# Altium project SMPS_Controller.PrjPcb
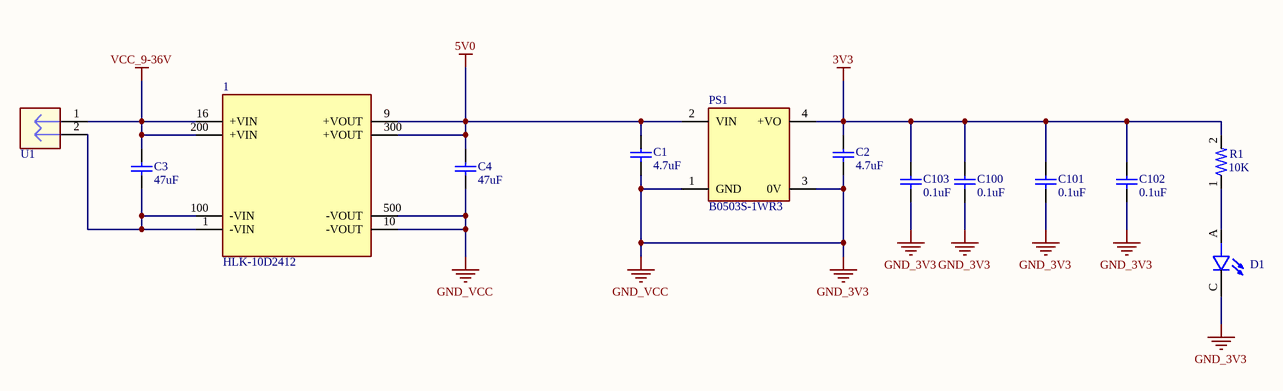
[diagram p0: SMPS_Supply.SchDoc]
11 sheets, 245 parts. Net scope: flat (ports and power ports of the same name join across sheets).
Board file: SMPS_Controller.PcbDoc
Sheets:
  SMPS_Supply.SchDoc
  SMPS_Connector.SchDoc
  SMPS_Voltage_1.SchDoc
  SMPS_Voltage_2.SchDoc
  SMPS_Voltage_3.SchDoc
  SMPS_Voltage_4.SchDoc
  SMPS_ADC_1.SchDoc
  SMPS_ADC_2.SchDoc
  SMPS_ADC_3.SchDoc
  SMPS_ADC_4.SchDoc
  SMPS_Signal.SchDoc

## Sheet SMPS_Supply.SchDoc
size A4; SheetNumber: 1; SheetTotal: 11

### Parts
1  HLK-10D2412  [HLK-10D2412]
C1  4.7uF  [CAP_0603]
C2  4.7uF  [CAP_0603]
C3  47uF  [CAP_1210]
C4  47uF  [CAP_1210]
C100  0.1uF  [CAP_0603]
C101  0.1uF  [CAP_0603]
C102  0.1uF  [CAP_0603]
C103  0.1uF  [CAP_0603]
D1  led_0603  [led_0603]  (value not drawn)
PS1  B0503S-1WR3  [B0503S-1W]
R1  10K  [RESC1608X50N]
U1  DG142R-5.08-02P  [DG142R-5.08-02P]  (value not drawn)

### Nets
3V3: C2.1 C100.1 C101.1 C102.1 C103.1 PS1.4(+VO) R1.2
5V0: 1.9(+VOUT) 1.300(+VOUT) C1.1 C4.2 PS1.2(VIN)
GND_3V3: 1.10(-VOUT) 1.500(-VOUT) C1.2 C2.2 C4.1 C100.2 C101.2 C102.2 C103.2 D1.C PS1.1(GND) PS1.3(0V)  [also labelled GND_VCC]
VCC_9-36V: 1.16(+VIN) 1.200(+VIN) C3.2 U1.1
Net1_1: 1.1(-VIN) 1.100(-VIN) C3.1 U1.2
NetD1_A: D1.A R1.1

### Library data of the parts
1 = HLK-10D2412: Isolated Module DC DC Converter Input: 9-24V   output: +12; MP: A1205S-2W; MF: Traco Power
C1 C2 C100-C103 = CAP_0603
C3 C4 = CAP_1210
D1 = led_0603: LED Indication - Discrete 3.1V 0603 _1608 Metric_; MP: LTW-C191TLA; MF: Lite-On
PS1 = B0505S-1WR3: Isolated Module DC DC Converter 1 Output 5V 200mA 4.5V - 5.5V Input; MF: Mornsun America, LLC
R1 = RES_0603: 1% 0.1W; MP: 1-2176071-4
U1 = DG142R-5.08-02P: DG129-5.0-03P-14-00AH

## Sheet SMPS_Connector.SchDoc
size A4; SheetNumber: 2; SheetTotal: 11
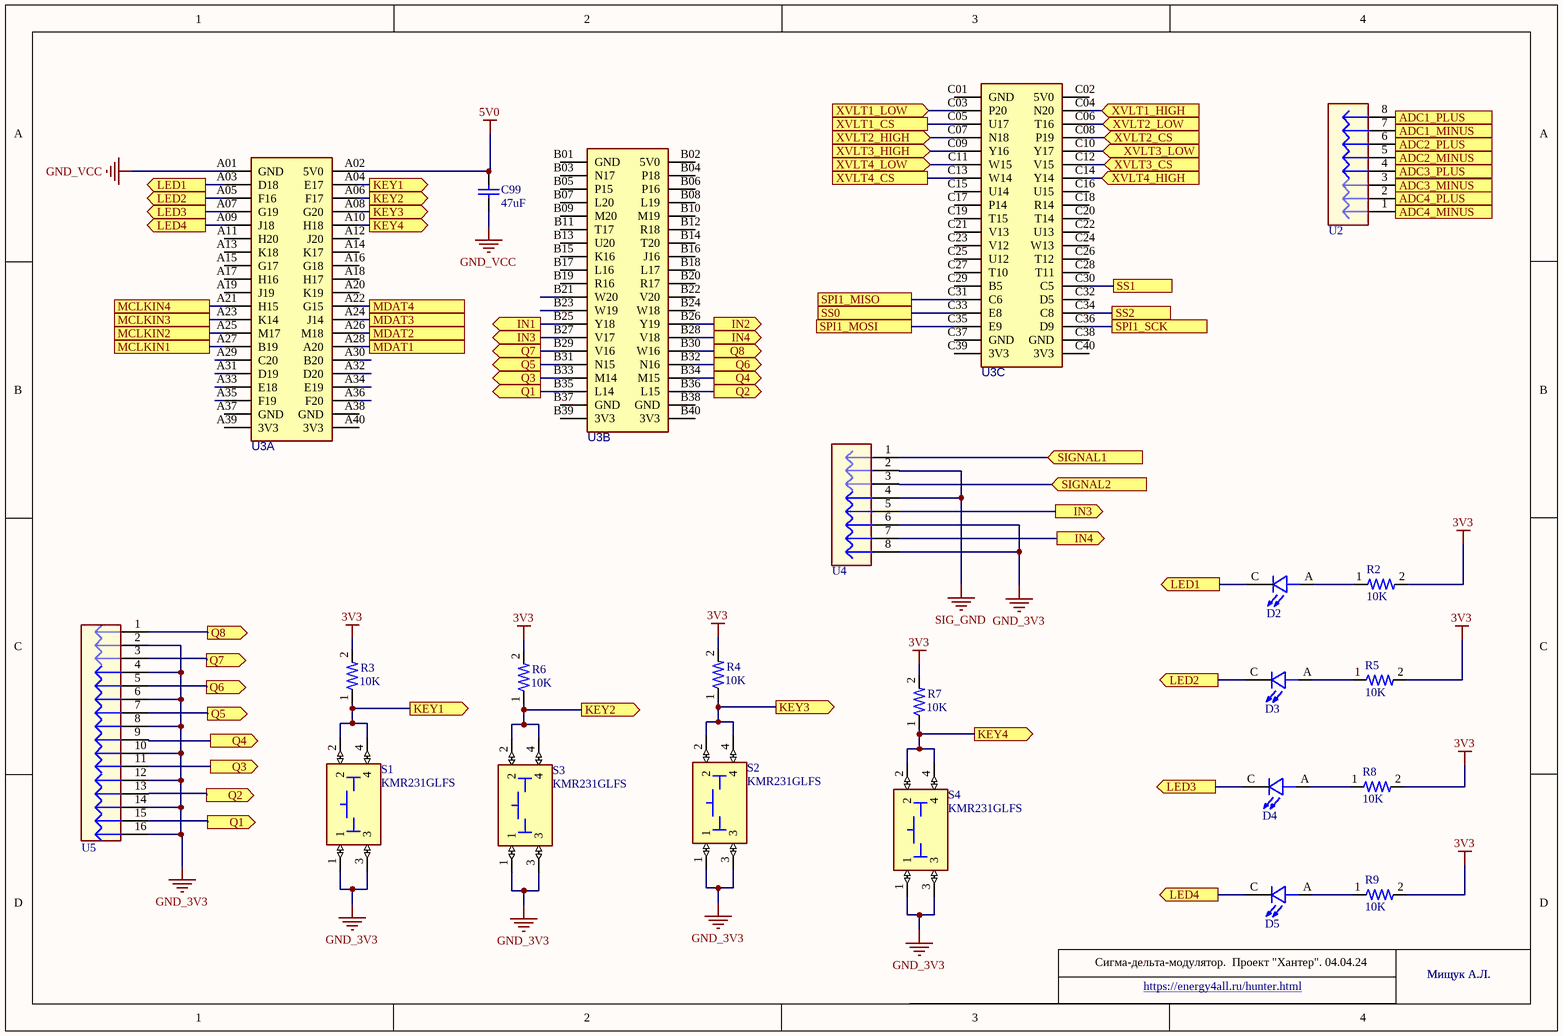
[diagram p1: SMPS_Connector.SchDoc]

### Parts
C99  47uF  [CAP_1210]
D2  led_0603  [led_0603]  (value not drawn)
D3  led_0603  [led_0603]  (value not drawn)
D4  led_0603  [led_0603]  (value not drawn)
D5  led_0603  [led_0603]  (value not drawn)
R2  10K  [RESC1608X50N]
R3  10K  [RESC1608X50N]
R4  10K  [RESC1608X50N]
R5  10K  [RESC1608X50N]
R6  10K  [RESC1608X50N]
R7  10K  [RESC1608X50N]
R8  10K  [RESC1608X50N]
R9  10K  [RESC1608X50N]
S1  KMR231GLFS  [KMR231GLFS]
S2  KMR231GLFS  [KMR231GLFS]
S3  KMR231GLFS  [KMR231GLFS]
S4  KMR231GLFS  [KMR231GLFS]
U2  DG142R-5.08-10P  [DG142R-5.08-10P]  (value not drawn)
U3  LGA506  [AC7020C]  (value not drawn)  (parts A,B,C of 3)
U4  DG141R-2.54-08P  [DG141R-2.54-08P]  (value not drawn)
U5  DG141R-2.54-16P  [DG141R-2.54-16P]  (value not drawn)

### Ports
ADC1_MINUS (out), ADC1_PLUS (out), ADC2_MINUS (out), ADC2_PLUS (out), ADC3_MINUS (out), ADC3_PLUS (out), ADC4_MINUS (out), ADC4_PLUS (out), IN1 (out), IN2 (out), IN3 (out), IN4 (out), KEY1 (out), KEY2 (out), KEY3 (out), KEY4 (out), LED1 (out), LED2 (out), LED3 (out), LED4 (out), MCLKIN1, MCLKIN2, MCLKIN3, MCLKIN4, MDAT1, MDAT2, MDAT3, MDAT4, Q1 (out), Q2 (out), Q3 (out), Q4 (out), Q5 (out), Q6 (out), Q7 (out), Q8 (out), SIGNAL1 (in), SIGNAL2 (in), SPI1_MISO, SPI1_MOSI, SPI1_SCK, SS0, SS1, SS2, XVLT1_CS, XVLT1_HIGH (in), XVLT1_LOW (in), XVLT2_CS (in), XVLT2_HIGH (in), XVLT2_LOW (in), XVLT3_CS (in), XVLT3_HIGH (in), XVLT3_LOW (in), XVLT4_CS, XVLT4_HIGH (in), XVLT4_LOW (in)

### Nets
3V3: R2.2 R3.2 R4.2 R5.2 R6.2 R7.2 R8.2 R9.2
5V0: C99.2 U3.A02(5V0)
GND_3V3: C99.1 S1.1 S1.3 S2.1 S2.3 S3.1 S3.3 S4.1 S4.3 U3.A01(GND) U4.6 U4.8 U5.2 U5.4 U5.6 U5.8 U5.10 U5.12 U5.14 U5.16  [also labelled GND_VCC]
SIG_GND: U4.2 U4.4
NetD2_A: D2.A R2.1
NetD2_C: D2.C U3.A03(D18) ; port LED1
NetD3_A: D3.A R5.1
NetD3_C: D3.C U3.A05(F16) ; port LED2
NetD4_A: D4.A R8.1
NetD4_C: D4.C U3.A07(G19) ; port LED3
NetD5_A: D5.A R9.1
NetD5_C: D5.C U3.A09(J18) ; port LED4
NetR3_1: R3.1 S1.2 S1.4 U3.A04(E17) ; port KEY1
NetR4_1: R4.1 S2.2 S2.4 U3.A08(G20) ; port KEY3
NetR6_1: R6.1 S3.2 S3.4 U3.A06(F17) ; port KEY2
NetR7_1: R7.1 S4.2 S4.4 U3.A10(H18) ; port KEY4
NetR46_1: U2.2 ; port ADC4_PLUS
NetR47_1: U3.A22(G15) ; port MDAT4
NetR48_1: U3.A21(H15) ; port MCLKIN4
NetR49_1: U2.1 ; port ADC4_MINUS
NetR52_1: U2.8 ; port ADC1_PLUS
NetR53_1: U3.A28(A20) ; port MDAT1
NetR54_1: U3.A27(B19) ; port MCLKIN1
NetR55_1: U2.7 ; port ADC1_MINUS
NetR58_1: U2.6 ; port ADC2_PLUS
NetR59_1: U3.A26(M18) ; port MDAT2
NetR60_1: U3.A25(M17) ; port MCLKIN2
NetR61_1: U2.5 ; port ADC2_MINUS
NetR64_1: U2.4 ; port ADC3_PLUS
NetR65_1: U3.A24(J14) ; port MDAT3
NetR66_1: U3.A23(K14) ; port MCLKIN3
NetR67_1: U2.3 ; port ADC3_MINUS
NetR70_1: U4.1 ; port SIGNAL1
NetR71_1: U4.3 ; port SIGNAL2
NetU3_B25: U3.B25(Y18) ; port IN1
NetU3_B26: U3.B26(Y19) ; port IN2
NetU3_B27: U3.B27(V17) U4.5 ; port IN3
NetU3_B28: U3.B28(V18) U4.7 ; port IN4
NetU3_B29: U3.B29(V16) U5.3 ; port Q7
NetU3_B30: U3.B30(W16) U5.1 ; port Q8
NetU3_B31: U3.B31(N15) U5.7 ; port Q5
NetU3_B32: U3.B32(N16) U5.5 ; port Q6
NetU3_B33: U3.B33(M14) U5.11 ; port Q3
NetU3_B34: U3.B34(M15) U5.9 ; port Q4
NetU3_B35: U3.B35(L14) U5.15 ; port Q1
NetU3_B36: U3.B36(L15) U5.13 ; port Q2
NetU3_C03: U3.C03(P20) ; port XVLT1_LOW
NetU3_C04: U3.C04(N20) ; port XVLT1_HIGH
NetU3_C05: U3.C05(U17) ; port XVLT1_CS
NetU3_C06: U3.C06(T16) ; port XVLT2_LOW
NetU3_C07: U3.C07(N18) ; port XVLT2_HIGH
NetU3_C08: U3.C08(P19) ; port XVLT2_CS
NetU3_C09: U3.C09(Y16) ; port XVLT3_HIGH
NetU3_C10: U3.C10(Y17) ; port XVLT3_LOW
NetU3_C11: U3.C11(W15) ; port XVLT4_LOW
NetU3_C12: U3.C12(V15) ; port XVLT3_CS
NetU3_C13: U3.C13(W14) ; port XVLT4_CS
NetU3_C14: U3.C14(Y14) ; port XVLT4_HIGH
NetU3_C30: U3.C30(C5) ; port SS1
NetU3_C31: U3.C31(C6) ; port SPI1_MISO
NetU3_C33: U3.C33(E8) ; port SS0
NetU3_C34: U3.C34(C8) ; port SS2
NetU3_C35: U3.C35(E9) ; port SPI1_MOSI
NetU3_C36: U3.C36(D9) ; port SPI1_SCK

Not connected (* = marked no-connect by the designer): U3 A11(H20) A12(J20) A13(K18) A14(K17) A15(G17) A16(G18) A17(H16) A18(H17) A19(J19) A20(K19) A29(C20) A30(B20) A31(D19) A32(D20) A33(E18) A34(E19) A35(F19) A36(F20) A37(GND) A38(GND) A39(3V3) A40(3V3) B01(GND) B02(5V0) B03(N17) B04(P18) B05(P15) B06(P16) B07(L20) B08(L19) B09(M20) B10(M19) B11(T17) B12(R18) B13(U20) B14(T20) B15(K16) B16(J16) B17(L16) B18(L17) B19(R16) B20(R17) B21(W20) B22(V20) B23(W19) B24(W18) B37(GND) B38(GND) B39(3V3) B40(3V3) C01(GND) C02(5V0) C15(U14) C16(U15) C17(P14) C18(R14) C19(T15) C20(T14) C21(V13) C22(U13) C23(V12) C24(W13) C25(U12) C26(T12) C27(T10) C28(T11) C29(B5) C32(D5) C37(GND) C38(GND) C39(3V3) C40(3V3)

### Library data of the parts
C99 = CAP_1210
D2-D5 = led_0603: as D1 on sheet SMPS_Supply
R2-R9 = RES_0603: 1% 0.1W; MP: 1-2176071-4
S1-S4 = KMR231GLFS: Tactile Switch SPST-NO Top Actuated Surface Mount; MF: C&K
U2 = DG142R-5.08-10P: DG129-5.0-03P-14-00AH
U3 = AC7020C
U4 = DG141R-2.54-08P: DG129-5.0-03P-14-00AH
U5 = DG141R-2.54-16P: DG129-5.0-03P-14-00AH

## Sheet SMPS_Voltage_1.SchDoc
size A4; SheetNumber: 3; SheetTotal: 11
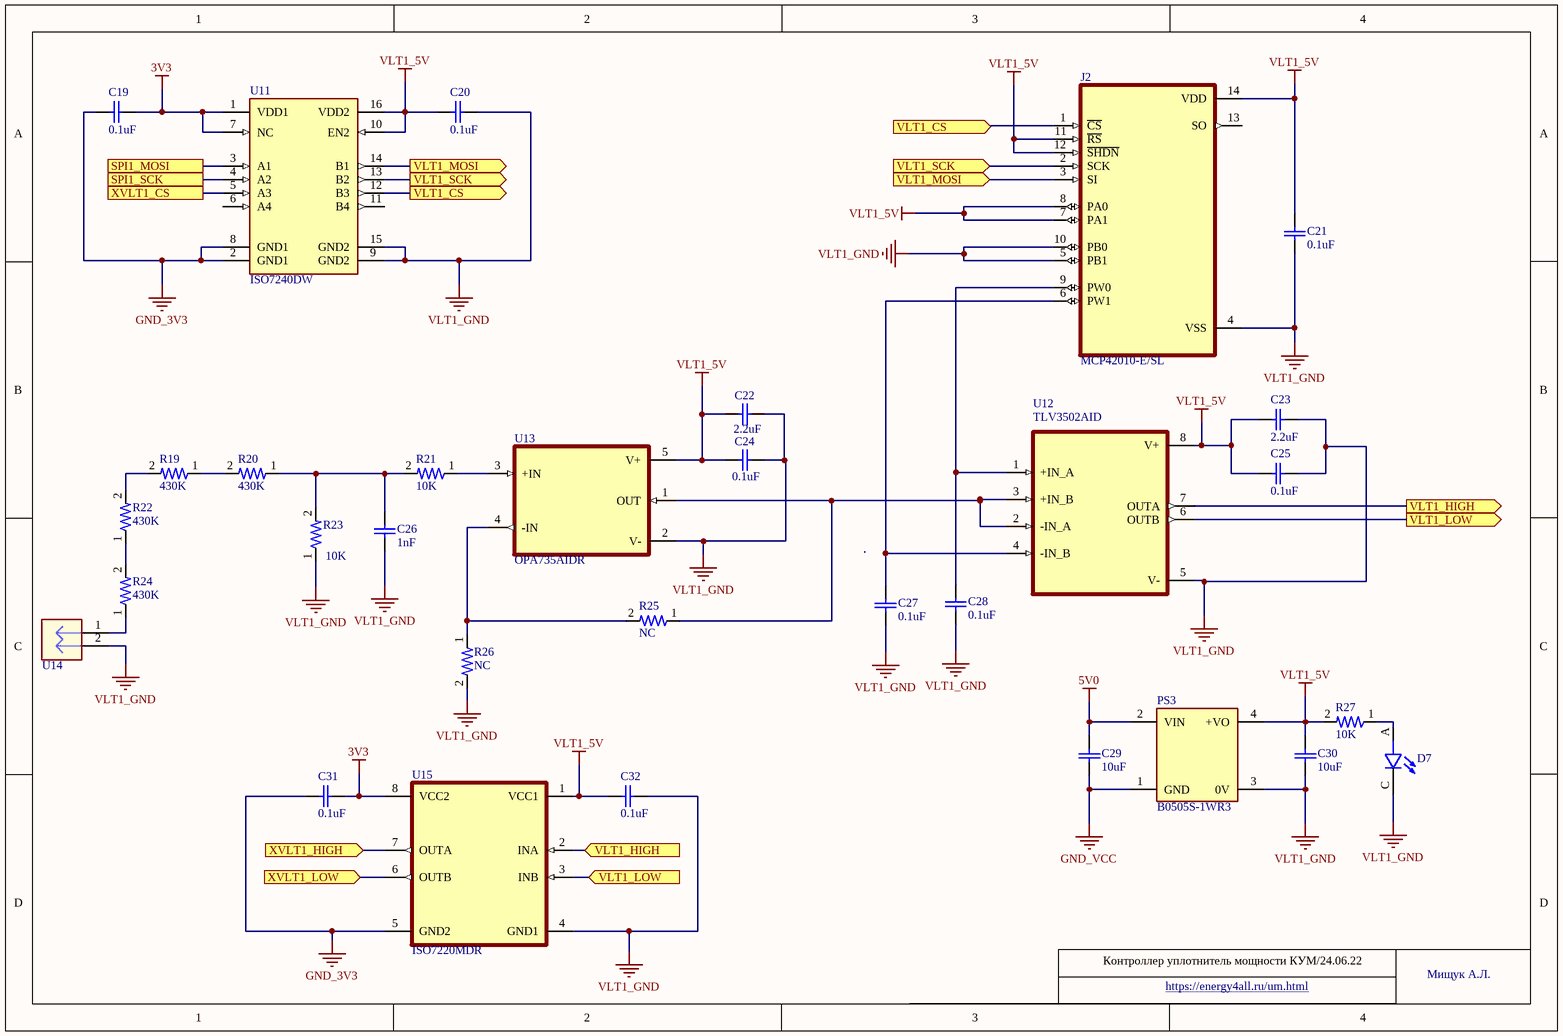
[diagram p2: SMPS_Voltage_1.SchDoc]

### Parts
C19  0.1uF  [CAP_0603]
C20  0.1uF  [CAP_0603]
C21  0.1uF  [CAP_0603]
C22  2.2uF  [CAP_0603]
C23  2.2uF  [CAP_0603]
C24  0.1uF  [CAP_0603]
C25  0.1uF  [CAP_0603]
C26  1nF  [CAP_0603]
C27  0.1uF  [CAP_0603]
C28  0.1uF  [CAP_0603]
C29  10uF  [CAP_0603]
C30  10uF  [CAP_0603]
C31  0.1uF  [CAP_0603]
C32  0.1uF  [CAP_0603]
D7  led_0603  [led_0603]  (value not drawn)
J2  MCP42010-E/SL  [SOP65P640X120-14N]
PS3  B0505S-1WR3  [B0503S-1W]
R19  430K  [RES_2512]
R20  430K  [RES_2512]
R21  10K  [RESC1608X50N]
R22  430K  [RES_2512]
R23  10K  [RES_1206]
R24  430K  [RES_2512]
R25  NC  [RESC1608X50N]
R26  NC  [RESC1608X50N]
R27  10K  [RESC1608X50N]
U11  ISO7240DW  [ISO7240DW]
U12  TLV3502AID  [TLV3502AID]
U13  OPA735AIDR  [OPA735AIDBVR]
U14  DG142R-5.08-02P  [DG142R-5.08-02P]  (value not drawn)
U15  ISO7220MDR  [ISO7220MDR]

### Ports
SPI1_MOSI, SPI1_SCK, VLT1_CS (in), VLT1_CS (out), VLT1_HIGH (in), VLT1_HIGH (out), VLT1_LOW (in), VLT1_LOW (out), VLT1_MOSI (in), VLT1_MOSI (out), VLT1_SCK (in), VLT1_SCK (out), XVLT1_CS, XVLT1_HIGH (in), XVLT1_LOW (in)

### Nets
3V3: C19.1 C31.1 U11.1(VDD1) U11.7(NC) U15.8(VCC2)
5V0: C29.2 PS3.2(VIN)
GND_3V3: C19.2 C29.1 C31.2 PS3.1(GND) U11.2(GND1) U11.8(GND1) U15.5(GND2)  [also labelled GND_VCC]
VLT1_5V: C20.2 C21.2 C22.1 C23.1 C24.1 C25.1 C30.2 C32.2 J2.7(PA1) J2.8(PA0) J2.11(~{RS}) J2.12(~{SHDN}) J2.14(VDD) PS3.4(+VO) R27.2 U11.10(EN2) U11.16(VDD2) U12.8(V+) U13.5(V+) U15.1(VCC1)
VLT1_GND: C20.1 C21.1 C22.2 C23.2 C24.2 C25.2 C26.2 C27.2 C28.2 C30.1 C32.1 D7.C J2.4(VSS) J2.5(PB1) J2.10(PB0) PS3.3(0V) R23.1 R26.2 U11.9(GND2) U11.15(GND2) U12.5(V-) U13.2(V-) U14.2 U15.4(GND1)
NetC26_1: C26.1 R20.1 R21.2 R23.2
NetC27_1: C27.1 J2.6(PW1) U12.4(-IN_B)
NetC28_1: C28.1 J2.9(PW0) U12.1(+IN_A)
NetD7_A: D7.A R27.1
NetJ2_1: J2.1(~{CS}) U11.12(B3) ; port VLT1_CS
NetJ2_2: J2.2(SCK) U11.13(B2) ; port VLT1_SCK
NetJ2_3: J2.3(SI) U11.14(B1) ; port VLT1_MOSI
NetR19_1: R19.1 R20.2
NetR19_2: R19.2 R22.2
NetR21_1: R21.1 U13.3(+IN)
NetR22_1: R22.1 R24.2
NetR24_1: R24.1 U14.1
NetR25_1: R25.1 U12.2(-IN_A) U12.3(+IN_B) U13.1(OUT)
NetR25_2: R25.2 R26.1 U13.4(-IN)
NetU3_C03: U15.6(OUTB) ; port XVLT1_LOW
NetU3_C04: U15.7(OUTA) ; port XVLT1_HIGH
NetU3_C05: U11.5(A3) ; port XVLT1_CS
NetU3_C35: U11.3(A1) ; port SPI1_MOSI
NetU3_C36: U11.4(A2) ; port SPI1_SCK
NetU12_6: U12.6(OUTB) U15.3(INB) ; port VLT1_LOW
NetU12_7: U12.7(OUTA) U15.2(INA) ; port VLT1_HIGH

Not connected (* = marked no-connect by the designer): J2 13(SO); U11 6(A4) 11(B4)

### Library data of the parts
C19-C32 = CAP_0603
D7 = led_0603: as D1 on sheet SMPS_Supply
J2 = MCP42010-E/SL: DIGITAL POT, 256 STEPS, SPI, 10KOHMS, DUAL CHANNEL ¦ Microchip Technology Inc. MCP42010-E/SL
PS3 = B0505S-1WR3: as PS1 on sheet SMPS_Supply
R19 R20 R22 R24 = RES_2512: 2512 1% 1W; MP: 1-2176071-4
R21 R25-R27 = RES_0603: 1% 0.1W; MP: 1-2176071-4
R23 = RES_1206: 1% 1/4W; MP: 1-2176071-4
U11 = ISO7240DW: MP: ISO7241CDWR
U12 = TLV3502AID: 4.5ns Rail-to-Rail Comparator; MF: Texas Instruments
U14 = DG142R-5.08-02P: DG129-5.0-03P-14-00AH
U15 = ISO7220MDR: Dual-channel, 2/0, 150-Mbps digital isolator 8-SOIC -40 to 125; MF: Texas Instruments

## Sheet SMPS_Voltage_2.SchDoc
size A4; SheetNumber: 4; SheetTotal: 11
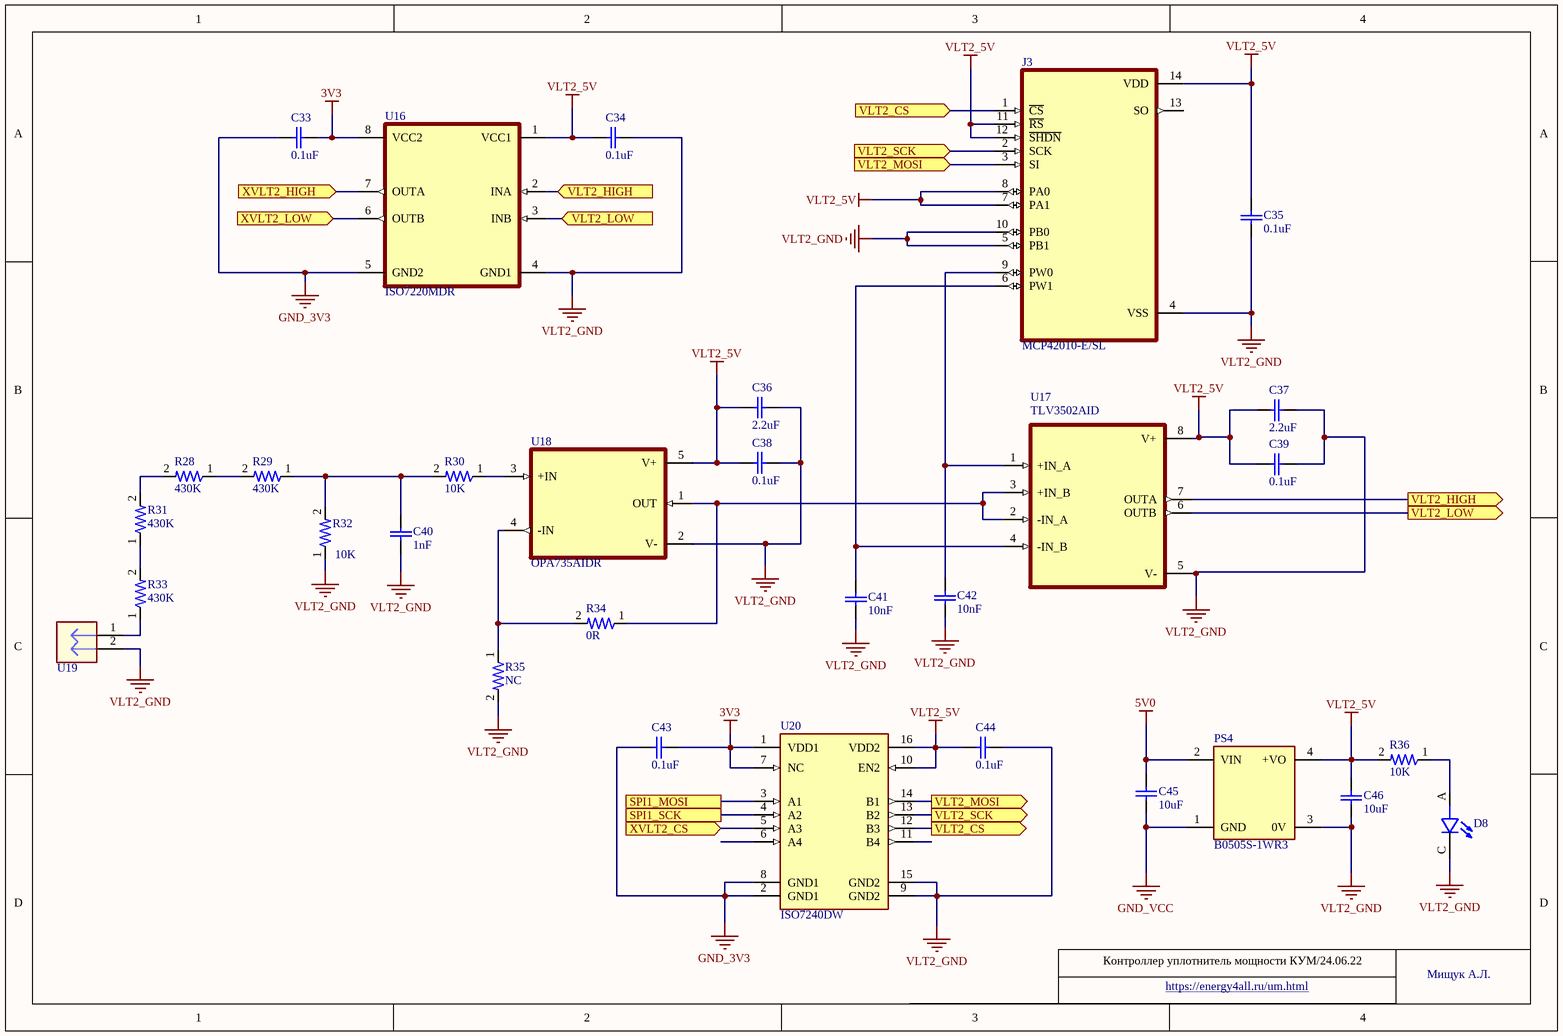
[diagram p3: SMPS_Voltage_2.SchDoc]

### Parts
C33  0.1uF  [CAP_0603]
C34  0.1uF  [CAP_0603]
C35  0.1uF  [CAP_0603]
C36  2.2uF  [CAP_0603]
C37  2.2uF  [CAP_0603]
C38  0.1uF  [CAP_0603]
C39  0.1uF  [CAP_0603]
C40  1nF  [CAP_0603]
C41  10nF  [CAP_0603]
C42  10nF  [CAP_0603]
C43  0.1uF  [CAP_0603]
C44  0.1uF  [CAP_0603]
C45  10uF  [CAP_0603]
C46  10uF  [CAP_0603]
D8  led_0603  [led_0603]  (value not drawn)
J3  MCP42010-E/SL  [SOP65P640X120-14N]
PS4  B0505S-1WR3  [B0503S-1W]
R28  430K  [RES_2512]
R29  430K  [RES_2512]
R30  10K  [RESC1608X50N]
R31  430K  [RES_2512]
R32  10K  [RES_1206]
R33  430K  [RES_2512]
R34  0R  [RESC1608X50N]
R35  NC  [RESC1608X50N]
R36  10K  [RESC1608X50N]
U16  ISO7220MDR  [ISO7220MDR]
U17  TLV3502AID  [TLV3502AID]
U18  OPA735AIDR  [OPA735AIDBVR]
U19  DG142R-5.08-02P  [DG142R-5.08-02P]  (value not drawn)
U20  ISO7240DW  [ISO7240DW]

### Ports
SPI1_MOSI, SPI1_SCK, VLT2_CS (in), VLT2_CS (out), VLT2_HIGH (in), VLT2_HIGH (out), VLT2_LOW (in), VLT2_LOW (out), VLT2_MOSI (in), VLT2_MOSI (out), VLT2_SCK (in), VLT2_SCK (out), XVLT2_CS (in), XVLT2_HIGH (in), XVLT2_LOW (in)

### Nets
3V3: C33.1 C43.1 U16.8(VCC2) U20.1(VDD1) U20.7(NC)
5V0: C45.2 PS4.2(VIN)
GND_3V3: C33.2 C43.2 C45.1 PS4.1(GND) U16.5(GND2) U20.2(GND1) U20.8(GND1)  [also labelled GND_VCC]
VLT2_5V: C34.2 C35.2 C36.1 C37.1 C38.1 C39.1 C44.2 C46.2 J3.7(PA1) J3.8(PA0) J3.11(~{RS}) J3.12(~{SHDN}) J3.14(VDD) PS4.4(+VO) R36.2 U16.1(VCC1) U17.8(V+) U18.5(V+) U20.10(EN2) U20.16(VDD2)
VLT2_GND: C34.1 C35.1 C36.2 C37.2 C38.2 C39.2 C40.2 C41.1 C42.1 C44.1 C46.1 D8.C J3.4(VSS) J3.5(PB1) J3.10(PB0) PS4.3(0V) R32.1 R35.2 U16.4(GND1) U17.5(V-) U18.2(V-) U19.2 U20.9(GND2) U20.15(GND2)
NetC40_1: C40.1 R29.1 R30.2 R32.2
NetC41_2: C41.2 J3.6(PW1) U17.4(-IN_B)
NetC42_2: C42.2 J3.9(PW0) U17.1(+IN_A)
NetD8_A: D8.A R36.1
NetJ3_1: J3.1(~{CS}) U20.12(B3) ; port VLT2_CS
NetJ3_2: J3.2(SCK) U20.13(B2) ; port VLT2_SCK
NetJ3_3: J3.3(SI) U20.14(B1) ; port VLT2_MOSI
NetR28_1: R28.1 R29.2
NetR28_2: R28.2 R31.2
NetR30_1: R30.1 U18.3(+IN)
NetR31_1: R31.1 R33.2
NetR33_1: R33.1 U19.1
NetR34_1: R34.1 U17.2(-IN_A) U17.3(+IN_B) U18.1(OUT)
NetR34_2: R34.2 R35.1 U18.4(-IN)
NetU3_C06: U16.6(OUTB) ; port XVLT2_LOW
NetU3_C07: U16.7(OUTA) ; port XVLT2_HIGH
NetU3_C08: U20.5(A3) ; port XVLT2_CS
NetU3_C35: U20.3(A1) ; port SPI1_MOSI
NetU3_C36: U20.4(A2) ; port SPI1_SCK
NetU16_2: U16.2(INA) U17.7(OUTA) ; port VLT2_HIGH
NetU16_3: U16.3(INB) U17.6(OUTB) ; port VLT2_LOW

Not connected (* = marked no-connect by the designer): J3 13(SO); U20 6(A4) 11(B4)

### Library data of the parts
C33-C46 = CAP_0603
D8 = led_0603: as D1 on sheet SMPS_Supply
J3 = MCP42010-E/SL: as J2 on sheet SMPS_Voltage_1
PS4 = B0505S-1WR3: as PS1 on sheet SMPS_Supply
R28 R29 R31 R33 = RES_2512: 2512 1% 1W; MP: 1-2176071-4
R30 R34-R36 = RES_0603: 1% 0.1W; MP: 1-2176071-4
R32 = RES_1206: 1% 1/4W; MP: 1-2176071-4
U16 = ISO7220MDR: as U15 on sheet SMPS_Voltage_1
U17 = TLV3502AID: as U12 on sheet SMPS_Voltage_1
U19 = DG142R-5.08-02P: DG129-5.0-03P-14-00AH
U20 = ISO7240DW: MP: ISO7241CDWR

## Sheet SMPS_Voltage_3.SchDoc
size A4; SheetNumber: 5; SheetTotal: 11
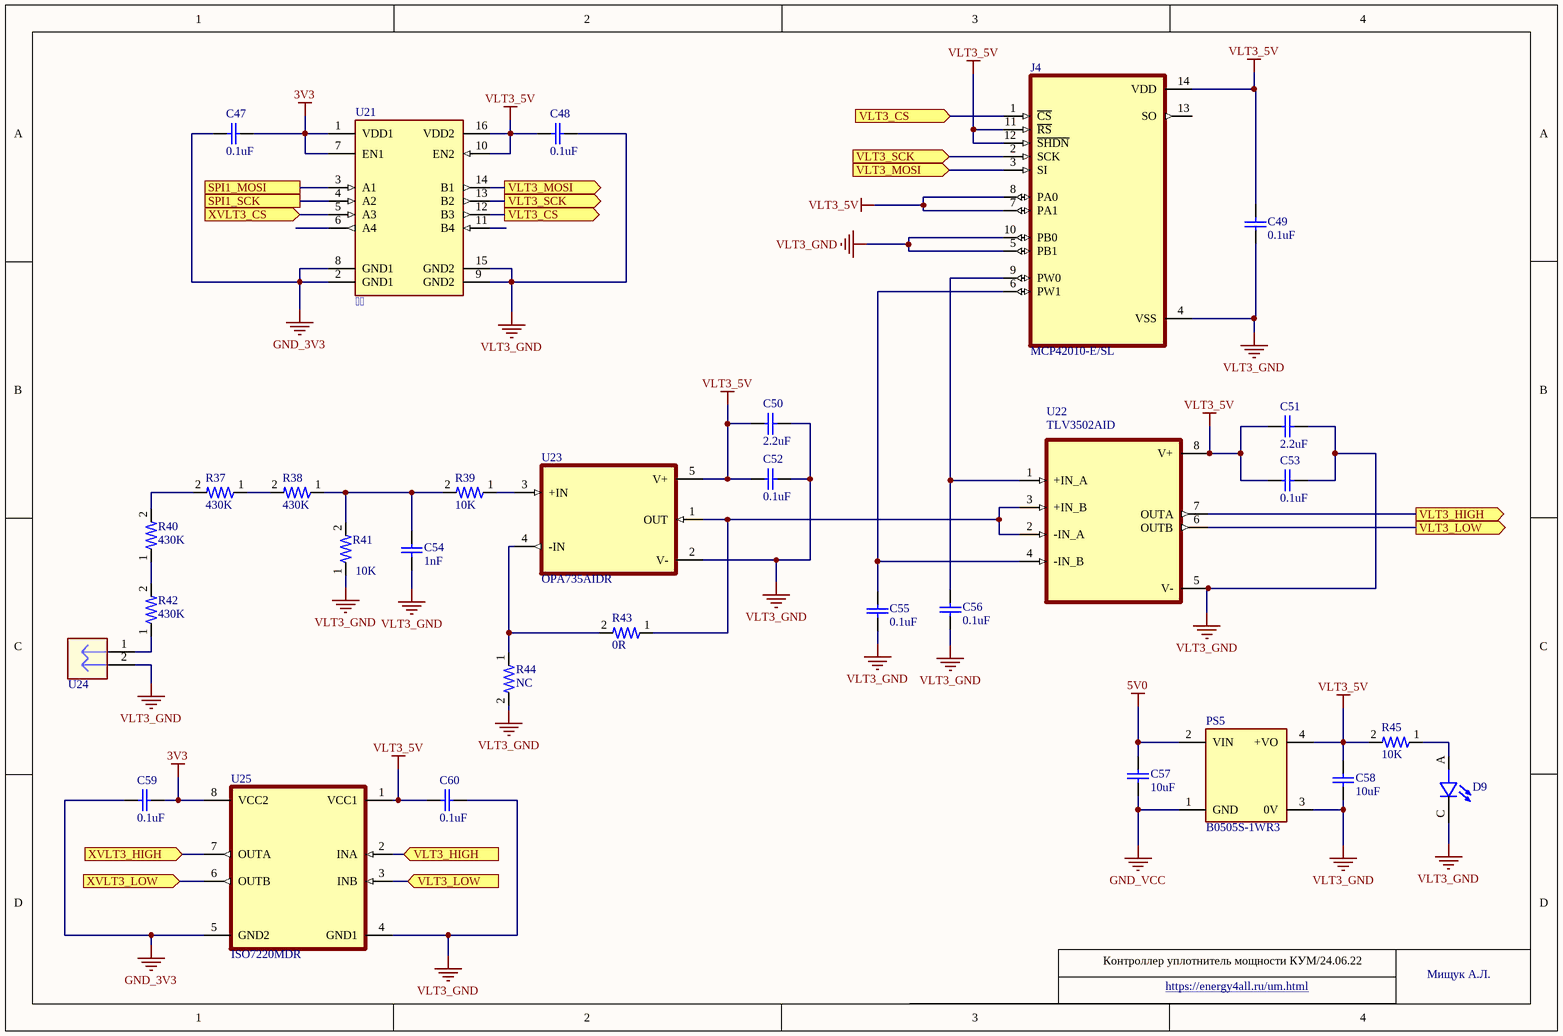
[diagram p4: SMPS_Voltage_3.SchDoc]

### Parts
C47  0.1uF  [CAP_0603]
C48  0.1uF  [CAP_0603]
C49  0.1uF  [CAP_0603]
C50  2.2uF  [CAP_0603]
C51  2.2uF  [CAP_0603]
C52  0.1uF  [CAP_0603]
C53  0.1uF  [CAP_0603]
C54  1nF  [CAP_0603]
C55  0.1uF  [CAP_0603]
C56  0.1uF  [CAP_0603]
C57  10uF  [CAP_0603]
C58  10uF  [CAP_0603]
C59  0.1uF  [CAP_0603]
C60  0.1uF  [CAP_0603]
D9  led_0603  [led_0603]  (value not drawn)
J4  MCP42010-E/SL  [SOP65P640X120-14N]
PS5  B0505S-1WR3  [B0503S-1W]
R37  430K  [RES_2512]
R38  430K  [RES_2512]
R39  10K  [RESC1608X50N]
R40  430K  [RES_2512]
R41  10K  [RES_1206]
R42  430K  [RES_2512]
R43  0R  [RESC1608X50N]
R44  NC  [RESC1608X50N]
R45  10K  [RESC1608X50N]
U21    [SI8641ED]
U22  TLV3502AID  [TLV3502AID]
U23  OPA735AIDR  [OPA735AIDBVR]
U24  DG142R-5.08-02P  [DG142R-5.08-02P]  (value not drawn)
U25  ISO7220MDR  [ISO7220MDR]

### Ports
SPI1_MOSI, SPI1_SCK, VLT3_CS (in), VLT3_CS (out), VLT3_HIGH (in), VLT3_HIGH (out), VLT3_LOW (in), VLT3_LOW (out), VLT3_MOSI (in), VLT3_MOSI (out), VLT3_SCK (in), VLT3_SCK (out), XVLT3_CS (in), XVLT3_HIGH (in), XVLT3_LOW (in)

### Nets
3V3: C47.1 C59.1 U21.1(VDD1) U21.7(EN1) U25.8(VCC2)
5V0: C57.2 PS5.2(VIN)
GND_3V3: C47.2 C57.1 C59.2 PS5.1(GND) U21.2(GND1) U21.8(GND1) U25.5(GND2)  [also labelled GND_VCC]
VLT3_5V: C48.2 C49.2 C50.1 C51.1 C52.1 C53.1 C58.2 C60.2 J4.7(PA1) J4.8(PA0) J4.11(~{RS}) J4.12(~{SHDN}) J4.14(VDD) PS5.4(+VO) R45.2 U21.10(EN2) U21.16(VDD2) U22.8(V+) U23.5(V+) U25.1(VCC1)
VLT3_GND: C48.1 C49.1 C50.2 C51.2 C52.2 C53.2 C54.2 C55.2 C56.2 C58.1 C60.1 D9.C J4.4(VSS) J4.5(PB1) J4.10(PB0) PS5.3(0V) R41.1 R44.2 U21.9(GND2) U21.15(GND2) U22.5(V-) U23.2(V-) U24.2 U25.4(GND1)
NetC54_1: C54.1 R38.1 R39.2 R41.2
NetC55_1: C55.1 J4.6(PW1) U22.4(-IN_B)
NetC56_1: C56.1 J4.9(PW0) U22.1(+IN_A)
NetD9_A: D9.A R45.1
NetJ4_1: J4.1(~{CS}) U21.12(B3) ; port VLT3_CS
NetJ4_2: J4.2(SCK) U21.13(B2) ; port VLT3_SCK
NetJ4_3: J4.3(SI) U21.14(B1) ; port VLT3_MOSI
NetR37_1: R37.1 R38.2
NetR37_2: R37.2 R40.2
NetR39_1: R39.1 U23.3(+IN)
NetR40_1: R40.1 R42.2
NetR42_1: R42.1 U24.1
NetR43_1: R43.1 U22.2(-IN_A) U22.3(+IN_B) U23.1(OUT)
NetR43_2: R43.2 R44.1 U23.4(-IN)
NetU3_C09: U25.7(OUTA) ; port XVLT3_HIGH
NetU3_C10: U25.6(OUTB) ; port XVLT3_LOW
NetU3_C12: U21.5(A3) ; port XVLT3_CS
NetU3_C35: U21.3(A1) ; port SPI1_MOSI
NetU3_C36: U21.4(A2) ; port SPI1_SCK
NetU22_6: U22.6(OUTB) U25.3(INB) ; port VLT3_LOW
NetU22_7: U22.7(OUTA) U25.2(INA) ; port VLT3_HIGH

Not connected (* = marked no-connect by the designer): J4 13(SO); U21 6(A4) 11(B4)

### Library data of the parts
C47-C60 = CAP_0603
D9 = led_0603: as D1 on sheet SMPS_Supply
J4 = MCP42010-E/SL: as J2 on sheet SMPS_Voltage_1
PS5 = B0505S-1WR3: as PS1 on sheet SMPS_Supply
R37 R38 R40 R42 = RES_2512: 2512 1% 1W; MP: 1-2176071-4
R39 R43-R45 = RES_0603: 1% 0.1W; MP: 1-2176071-4
R41 = RES_1206: 1% 1/4W; MP: 1-2176071-4
U21 = SI8641ED: General Purpose Digital Isolator 2500Vrms 4 Channel 150Mbps 35kV/Âµs CMTI 16-SOIC _0.154, 3.90mm Width_; MP: SI8641BB-B-IS1; MF: Silicon Labs
U22 = TLV3502AID: as U12 on sheet SMPS_Voltage_1
U24 = DG142R-5.08-02P: DG129-5.0-03P-14-00AH
U25 = ISO7220MDR: as U15 on sheet SMPS_Voltage_1

## Sheet SMPS_Voltage_4.SchDoc
size A4; SheetNumber: 6; SheetTotal: 11
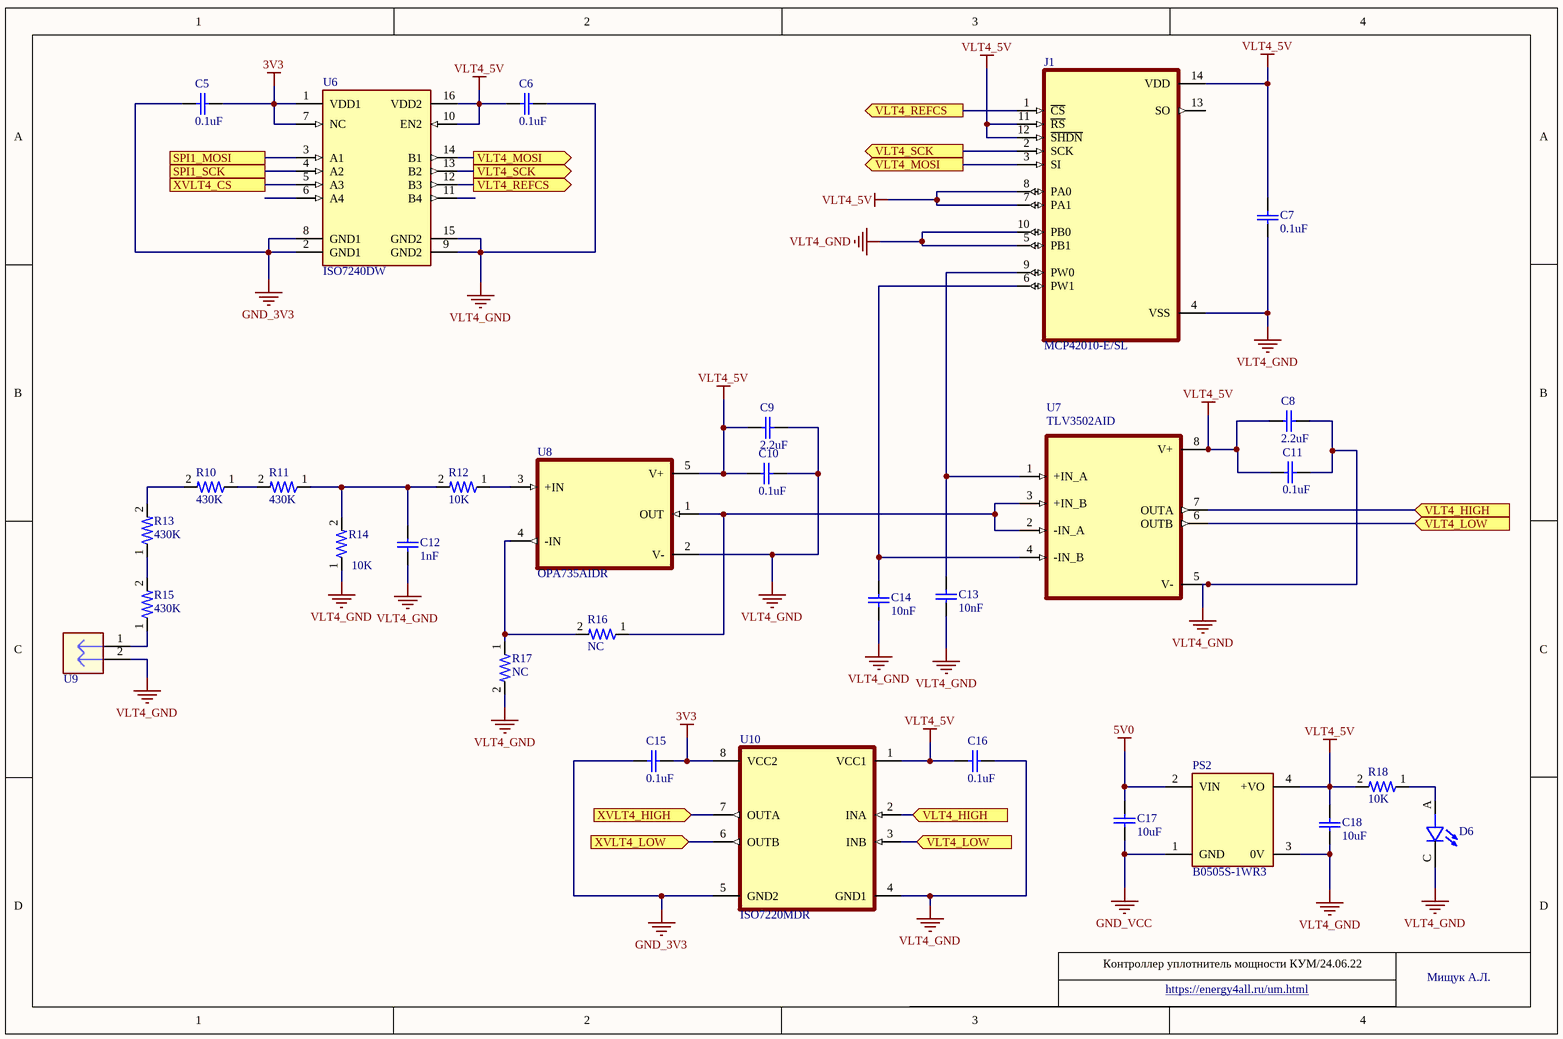
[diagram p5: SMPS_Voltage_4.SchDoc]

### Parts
C5  0.1uF  [CAP_0603]
C6  0.1uF  [CAP_0603]
C7  0.1uF  [CAP_0603]
C8  2.2uF  [CAP_0603]
C9  2.2uF  [CAP_0603]
C10  0.1uF  [CAP_0603]
C11  0.1uF  [CAP_0603]
C12  1nF  [CAP_0603]
C13  10nF  [CAP_0603]
C14  10nF  [CAP_0603]
C15  0.1uF  [CAP_0603]
C16  0.1uF  [CAP_0603]
C17  10uF  [CAP_0603]
C18  10uF  [CAP_0603]
D6  led_0603  [led_0603]  (value not drawn)
J1  MCP42010-E/SL  [SOP65P640X120-14N]
PS2  B0505S-1WR3  [B0503S-1W]
R10  430K  [RES_2512]
R11  430K  [RES_2512]
R12  10K  [RESC1608X50N]
R13  430K  [RES_2512]
R14  10K  [RES_1206]
R15  430K  [RES_2512]
R16  NC  [RESC1608X50N]
R17  NC  [RESC1608X50N]
R18  10K  [RESC1608X50N]
U6  ISO7240DW  [ISO7240DW]
U7  TLV3502AID  [TLV3502AID]
U8  OPA735AIDR  [OPA735AIDBVR]
U9  DG142R-5.08-02P  [DG142R-5.08-02P]  (value not drawn)
U10  ISO7220MDR  [ISO7220MDR]

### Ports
SPI1_MOSI, SPI1_SCK, VLT4_HIGH (in), VLT4_LOW (in), VLT4_MOSI (out), VLT4_REFCS (out), VLT4_SCK (out), XVLT4_CS, XVLT4_HIGH (in), XVLT4_LOW (in)

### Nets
3V3: C5.1 C15.1 U6.1(VDD1) U6.7(NC) U10.8(VCC2)
5V0: C17.2 PS2.2(VIN)
GND_3V3: C5.2 C15.2 C17.1 PS2.1(GND) U6.2(GND1) U6.8(GND1) U10.5(GND2)  [also labelled GND_VCC]
VLT4_5V: C6.2 C7.2 C8.1 C9.1 C10.1 C11.1 C16.2 C18.2 J1.7(PA1) J1.8(PA0) J1.11(~{RS}) J1.12(~{SHDN}) J1.14(VDD) PS2.4(+VO) R18.2 U6.10(EN2) U6.16(VDD2) U7.8(V+) U8.5(V+) U10.1(VCC1)
VLT4_GND: C6.1 C7.1 C8.2 C9.2 C10.2 C11.2 C12.2 C13.1 C14.2 C16.1 C18.1 D6.C J1.4(VSS) J1.5(PB1) J1.10(PB0) PS2.3(0V) R14.1 R17.2 U6.9(GND2) U6.15(GND2) U7.5(V-) U8.2(V-) U9.2 U10.4(GND1)
NetC12_1: C12.1 R11.1 R12.2 R14.2
NetC13_2: C13.2 J1.9(PW0) U7.1(+IN_A)
NetC14_1: C14.1 J1.6(PW1) U7.4(-IN_B)
NetD6_A: D6.A R18.1
NetJ1_1: J1.1(~{CS}) U6.12(B3) ; port VLT4_REFCS
NetJ1_2: J1.2(SCK) U6.13(B2) ; port VLT4_SCK
NetJ1_3: J1.3(SI) U6.14(B1) ; port VLT4_MOSI
NetR10_1: R10.1 R11.2
NetR10_2: R10.2 R13.2
NetR12_1: R12.1 U8.3(+IN)
NetR13_1: R13.1 R15.2
NetR15_1: R15.1 U9.1
NetR16_1: R16.1 U7.2(-IN_A) U7.3(+IN_B) U8.1(OUT)
NetR16_2: R16.2 R17.1 U8.4(-IN)
NetU3_C11: U10.6(OUTB) ; port XVLT4_LOW
NetU3_C13: U6.5(A3) ; port XVLT4_CS
NetU3_C14: U10.7(OUTA) ; port XVLT4_HIGH
NetU3_C35: U6.3(A1) ; port SPI1_MOSI
NetU3_C36: U6.4(A2) ; port SPI1_SCK
NetU7_6: U7.6(OUTB) U10.3(INB) ; port VLT4_LOW
NetU7_7: U7.7(OUTA) U10.2(INA) ; port VLT4_HIGH

Not connected (* = marked no-connect by the designer): J1 13(SO); U6 6(A4) 11(B4)

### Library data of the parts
C5-C18 = CAP_0603
D6 = led_0603: as D1 on sheet SMPS_Supply
J1 = MCP42010-E/SL: as J2 on sheet SMPS_Voltage_1
PS2 = B0505S-1WR3: as PS1 on sheet SMPS_Supply
R10 R11 R13 R15 = RES_2512: 2512 1% 1W; MP: 1-2176071-4
R12 R16-R18 = RES_0603: 1% 0.1W; MP: 1-2176071-4
R14 = RES_1206: 1% 1/4W; MP: 1-2176071-4
U6 = ISO7240DW: MP: ISO7241CDWR
U7 = TLV3502AID: as U12 on sheet SMPS_Voltage_1
U9 = DG142R-5.08-02P: DG129-5.0-03P-14-00AH
U10 = ISO7220MDR: as U15 on sheet SMPS_Voltage_1

## Sheet SMPS_ADC_1.SchDoc
size A4; SheetNumber: 7; SheetTotal: 11
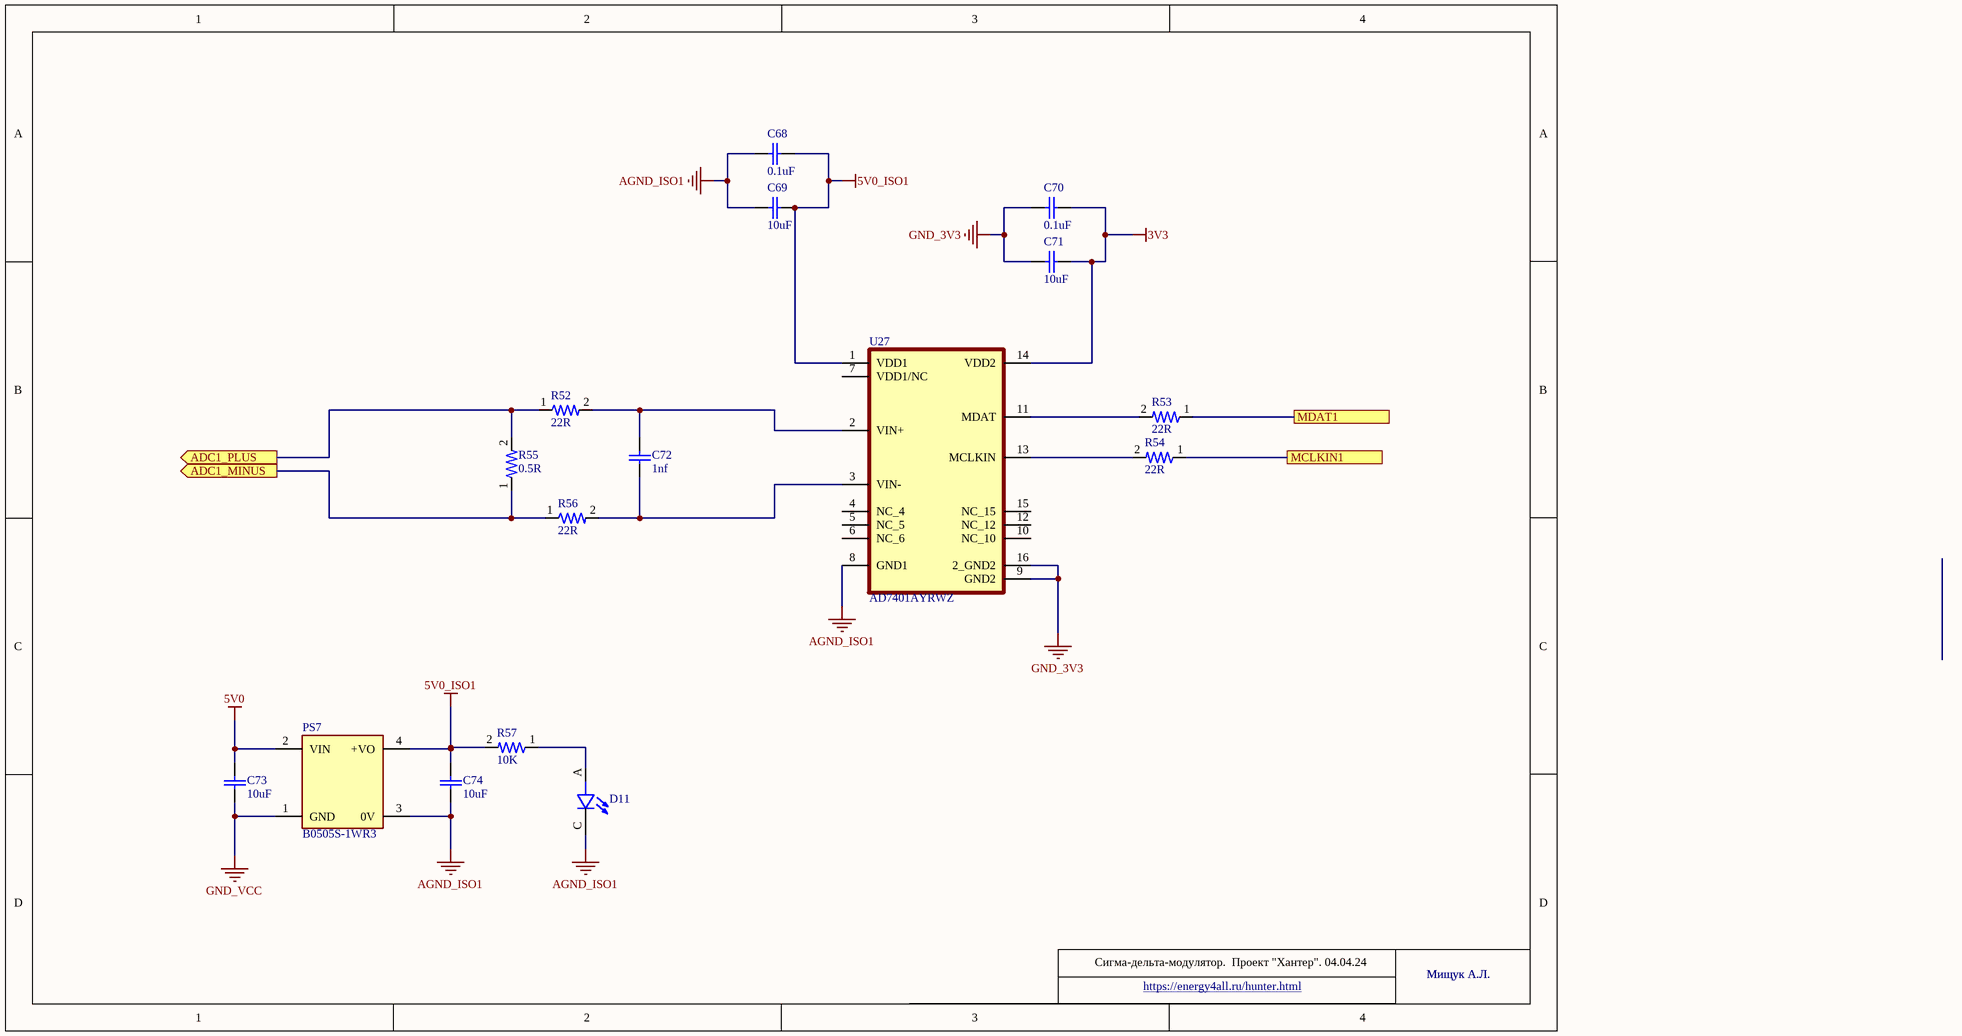
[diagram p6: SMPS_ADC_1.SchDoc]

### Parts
C68  0.1uF  [CAP_0603]
C69  10uF  [CAP_0603]
C70  0.1uF  [CAP_0603]
C71  10uF  [CAP_0603]
C72  1nf  [CAP_0603]
C73  10uF  [CAP_0603]
C74  10uF  [CAP_0603]
D11  led_0603  [led_0603]  (value not drawn)
PS7  B0505S-1WR3  [B0503S-1W]
R52  22R  [RESC1608X50N]
R53  22R  [RESC1608X50N]
R54  22R  [RESC1608X50N]
R55  0.5R  [RES_2512]
R56  22R  [RESC1608X50N]
R57  10K  [RESC1608X50N]
U27  AD7401AYRWZ  [AD7401AYRWZ]

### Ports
ADC1_MINUS (out), ADC1_PLUS (out), MCLKIN1, MDAT1

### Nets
3V3: C70.1 C71.1 U27.14(VDD2)
5V0: C73.2 PS7.2(VIN)
5V0_ISO1: C68.1 C69.1 C74.2 PS7.4(+VO) R57.2 U27.1(VDD1)
AGND_ISO1: C68.2 C69.2 C74.1 D11.C PS7.3(0V) U27.8(GND1)
GND_3V3: C70.2 C71.2 C73.1 PS7.1(GND) U27.9(GND2) U27.16(2_GND2)  [also labelled GND_VCC]
NetC72_1: C72.1 R56.2 U27.3(VIN-)
NetC72_2: C72.2 R52.2 U27.2(VIN+)
NetD11_A: D11.A R57.1
NetR52_1: R52.1 R55.2 ; port ADC1_PLUS
NetR53_1: R53.1 ; port MDAT1
NetR53_2: R53.2 U27.11(MDAT)
NetR54_1: R54.1 ; port MCLKIN1
NetR54_2: R54.2 U27.13(MCLKIN)
NetR55_1: R55.1 R56.1 ; port ADC1_MINUS

Not connected (* = marked no-connect by the designer): U27 4(NC_4) 5(NC_5) 6(NC_6) 7(VDD1/NC) 10(NC_10) 12(NC_12) 15(NC_15)

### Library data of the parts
C68-C74 = CAP_0603
D11 = led_0603: as D1 on sheet SMPS_Supply
PS7 = B0505S-1WR3: as PS1 on sheet SMPS_Supply
R52-R54 R56 R57 = RES_0603: 1% 0.1W; MP: 1-2176071-4
R55 = RES_2512: 2512 1% 1W; MP: 1-2176071-4
U27 = AD7401YRWZ: Isolated Module 16 b Serial 16-SOIC; MF: Analog Devices; MP: AD7401YRWZ-REEL7

## Sheet SMPS_ADC_2.SchDoc
size A4; SheetNumber: 8; SheetTotal: 11
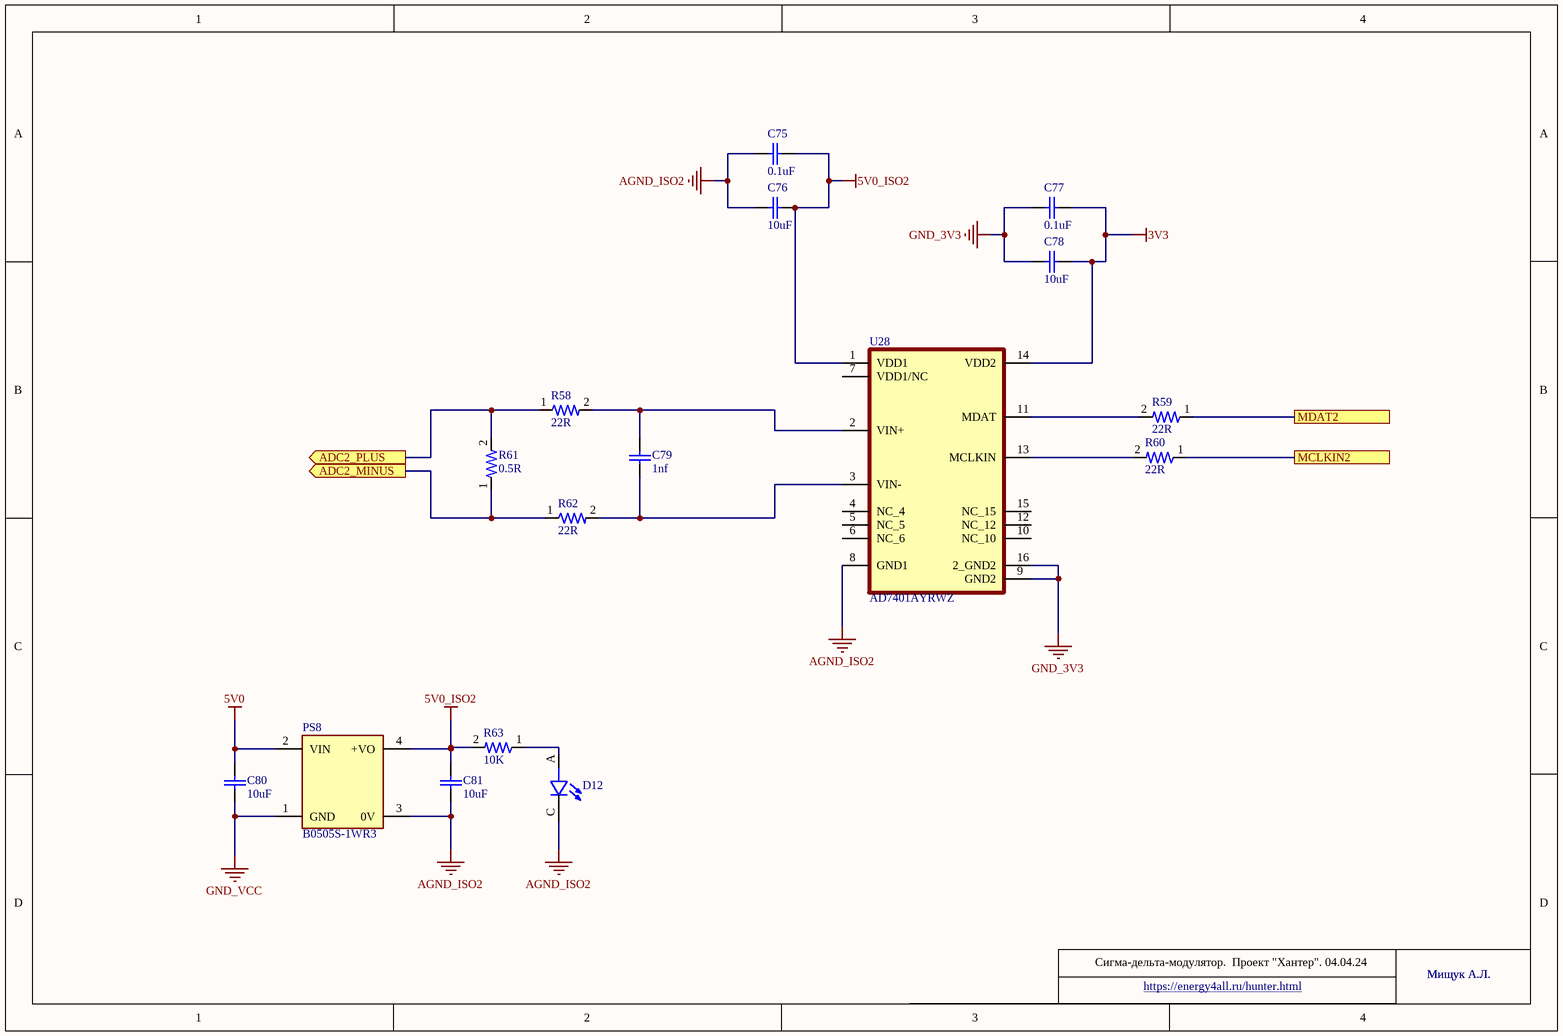
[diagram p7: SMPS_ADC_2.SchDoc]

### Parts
C75  0.1uF  [CAP_0603]
C76  10uF  [CAP_0603]
C77  0.1uF  [CAP_0603]
C78  10uF  [CAP_0603]
C79  1nf  [CAP_0603]
C80  10uF  [CAP_0603]
C81  10uF  [CAP_0603]
D12  led_0603  [led_0603]  (value not drawn)
PS8  B0505S-1WR3  [B0503S-1W]
R58  22R  [RESC1608X50N]
R59  22R  [RESC1608X50N]
R60  22R  [RESC1608X50N]
R61  0.5R  [RES_2512]
R62  22R  [RESC1608X50N]
R63  10K  [RESC1608X50N]
U28  AD7401AYRWZ  [AD7401AYRWZ]

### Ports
ADC2_MINUS (out), ADC2_PLUS (out), MCLKIN2, MDAT2

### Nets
3V3: C77.1 C78.1 U28.14(VDD2)
5V0: C80.2 PS8.2(VIN)
5V0_ISO2: C75.1 C76.1 C81.2 PS8.4(+VO) R63.2 U28.1(VDD1)
AGND_ISO2: C75.2 C76.2 C81.1 D12.C PS8.3(0V) U28.8(GND1)
GND_3V3: C77.2 C78.2 C80.1 PS8.1(GND) U28.9(GND2) U28.16(2_GND2)  [also labelled GND_VCC]
NetC79_1: C79.1 R62.2 U28.3(VIN-)
NetC79_2: C79.2 R58.2 U28.2(VIN+)
NetD12_A: D12.A R63.1
NetR58_1: R58.1 R61.2 ; port ADC2_PLUS
NetR59_1: R59.1 ; port MDAT2
NetR59_2: R59.2 U28.11(MDAT)
NetR60_1: R60.1 ; port MCLKIN2
NetR60_2: R60.2 U28.13(MCLKIN)
NetR61_1: R61.1 R62.1 ; port ADC2_MINUS

Not connected (* = marked no-connect by the designer): U28 4(NC_4) 5(NC_5) 6(NC_6) 7(VDD1/NC) 10(NC_10) 12(NC_12) 15(NC_15)

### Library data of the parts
C75-C81 = CAP_0603
D12 = led_0603: as D1 on sheet SMPS_Supply
PS8 = B0505S-1WR3: as PS1 on sheet SMPS_Supply
R58-R60 R62 R63 = RES_0603: 1% 0.1W; MP: 1-2176071-4
R61 = RES_2512: 2512 1% 1W; MP: 1-2176071-4
U28 = AD7401YRWZ: as U27 on sheet SMPS_ADC_1

## Sheet SMPS_ADC_3.SchDoc
size A4; SheetNumber: 9; SheetTotal: 11
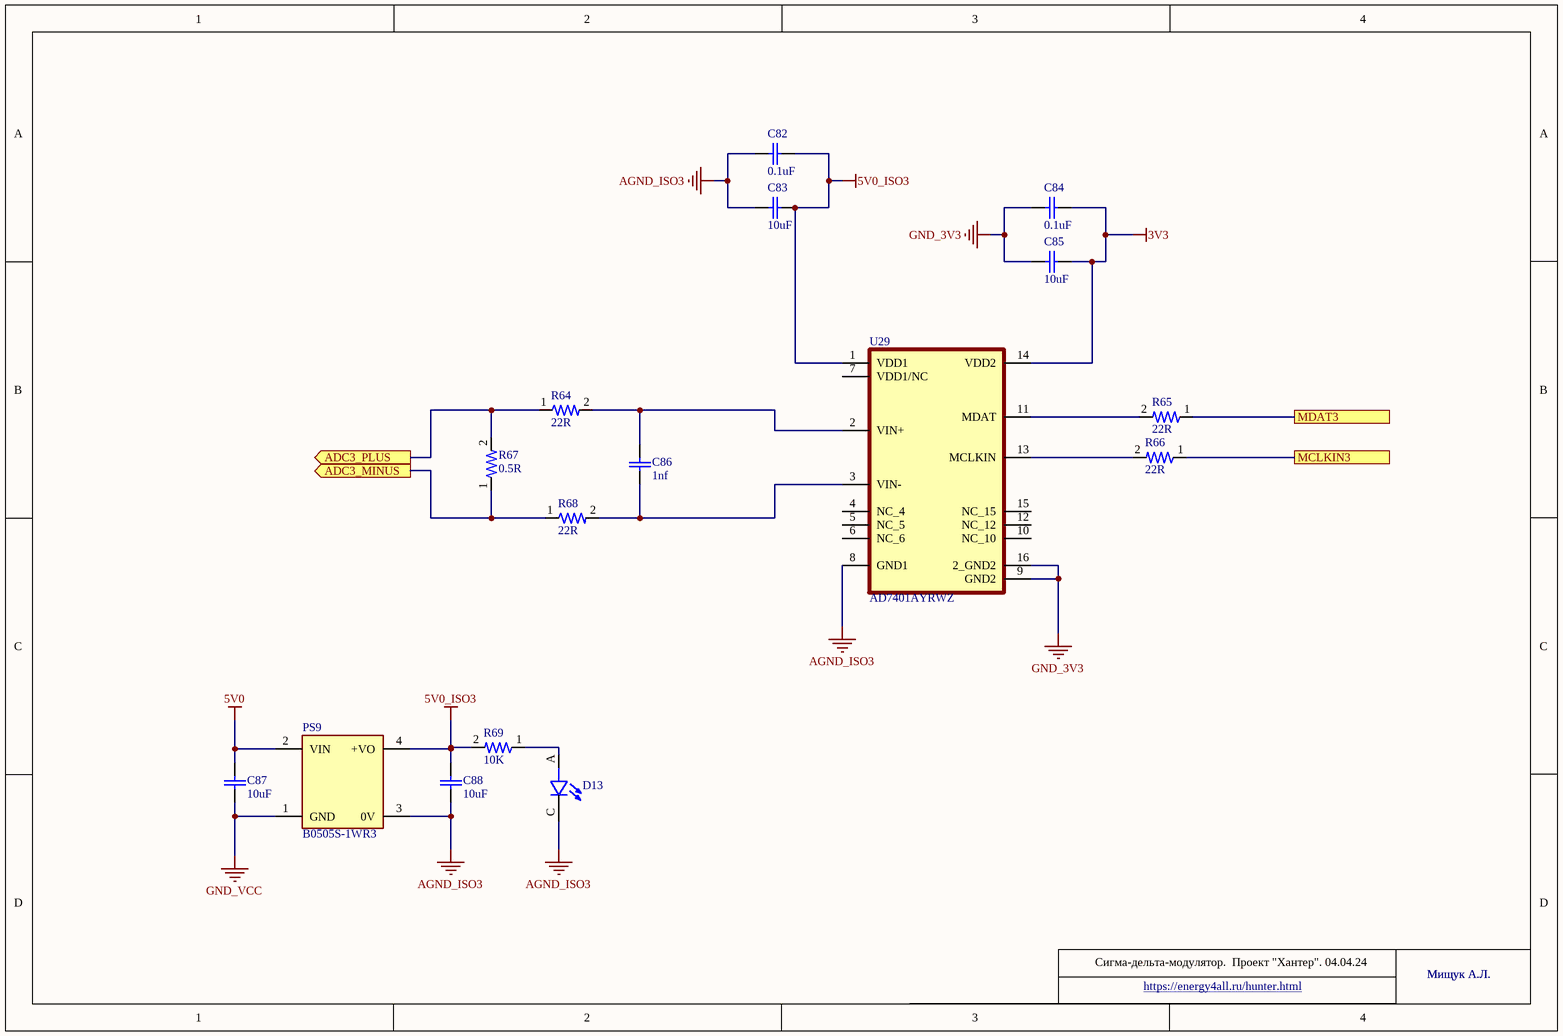
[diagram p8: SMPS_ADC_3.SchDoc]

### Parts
C82  0.1uF  [CAP_0603]
C83  10uF  [CAP_0603]
C84  0.1uF  [CAP_0603]
C85  10uF  [CAP_0603]
C86  1nf  [CAP_0603]
C87  10uF  [CAP_0603]
C88  10uF  [CAP_0603]
D13  led_0603  [led_0603]  (value not drawn)
PS9  B0505S-1WR3  [B0503S-1W]
R64  22R  [RESC1608X50N]
R65  22R  [RESC1608X50N]
R66  22R  [RESC1608X50N]
R67  0.5R  [RES_2512]
R68  22R  [RESC1608X50N]
R69  10K  [RESC1608X50N]
U29  AD7401AYRWZ  [AD7401AYRWZ]

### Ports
ADC3_MINUS (out), ADC3_PLUS (out), MCLKIN3, MDAT3

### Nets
3V3: C84.1 C85.1 U29.14(VDD2)
5V0: C87.2 PS9.2(VIN)
5V0_ISO3: C82.1 C83.1 C88.2 PS9.4(+VO) R69.2 U29.1(VDD1)
AGND_ISO3: C82.2 C83.2 C88.1 D13.C PS9.3(0V) U29.8(GND1)
GND_3V3: C84.2 C85.2 C87.1 PS9.1(GND) U29.9(GND2) U29.16(2_GND2)  [also labelled GND_VCC]
NetC86_1: C86.1 R68.2 U29.3(VIN-)
NetC86_2: C86.2 R64.2 U29.2(VIN+)
NetD13_A: D13.A R69.1
NetR64_1: R64.1 R67.2 ; port ADC3_PLUS
NetR65_1: R65.1 ; port MDAT3
NetR65_2: R65.2 U29.11(MDAT)
NetR66_1: R66.1 ; port MCLKIN3
NetR66_2: R66.2 U29.13(MCLKIN)
NetR67_1: R67.1 R68.1 ; port ADC3_MINUS

Not connected (* = marked no-connect by the designer): U29 4(NC_4) 5(NC_5) 6(NC_6) 7(VDD1/NC) 10(NC_10) 12(NC_12) 15(NC_15)

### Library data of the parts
C82-C88 = CAP_0603
D13 = led_0603: as D1 on sheet SMPS_Supply
PS9 = B0505S-1WR3: as PS1 on sheet SMPS_Supply
R64-R66 R68 R69 = RES_0603: 1% 0.1W; MP: 1-2176071-4
R67 = RES_2512: 2512 1% 1W; MP: 1-2176071-4
U29 = AD7401YRWZ: as U27 on sheet SMPS_ADC_1

## Sheet SMPS_ADC_4.SchDoc
size A4; SheetNumber: 10; SheetTotal: 11
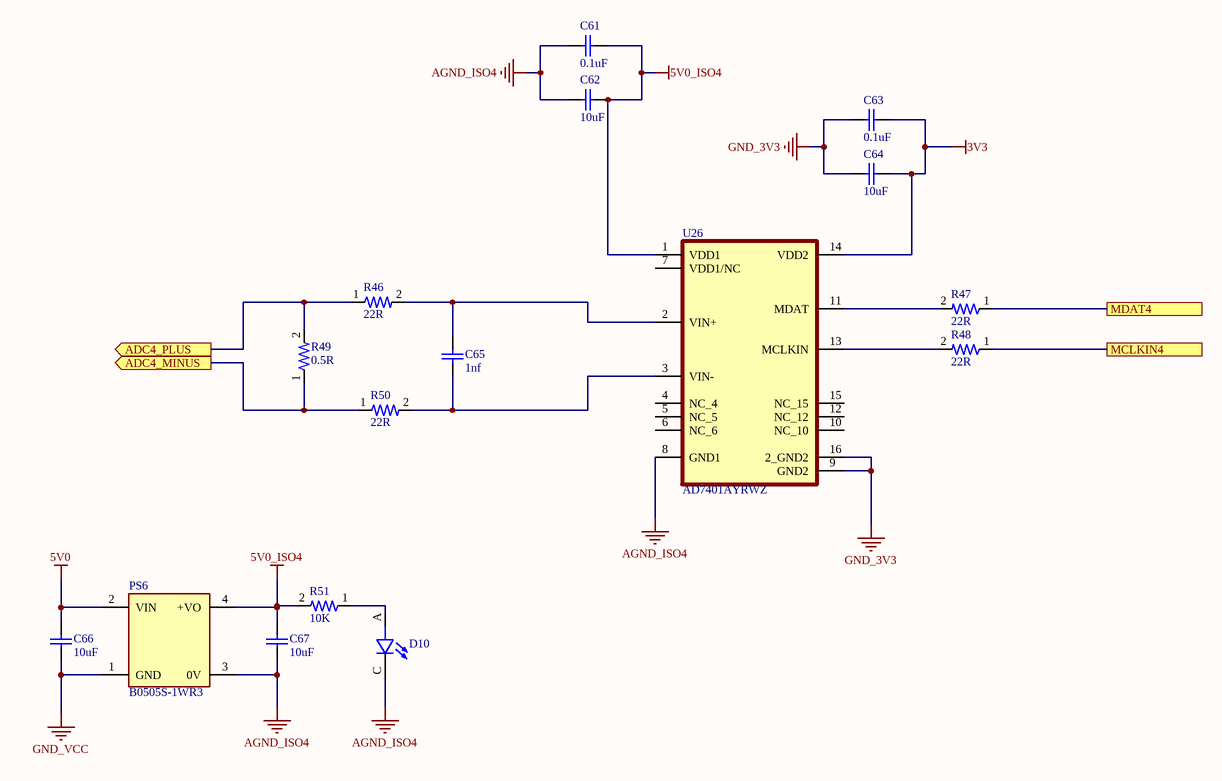
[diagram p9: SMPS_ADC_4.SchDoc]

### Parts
C61  0.1uF  [CAP_0603]
C62  10uF  [CAP_0603]
C63  0.1uF  [CAP_0603]
C64  10uF  [CAP_0603]
C65  1nf  [CAP_0603]
C66  10uF  [CAP_0603]
C67  10uF  [CAP_0603]
D10  led_0603  [led_0603]  (value not drawn)
PS6  B0505S-1WR3  [B0503S-1W]
R46  22R  [RESC1608X50N]
R47  22R  [RESC1608X50N]
R48  22R  [RESC1608X50N]
R49  0.5R  [RES_2512]
R50  22R  [RESC1608X50N]
R51  10K  [RESC1608X50N]
U26  AD7401AYRWZ  [AD7401AYRWZ]

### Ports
ADC4_MINUS (out), ADC4_PLUS (out), MCLKIN4, MDAT4

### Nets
3V3: C63.1 C64.1 U26.14(VDD2)
5V0: C66.2 PS6.2(VIN)
5V0_ISO4: C61.1 C62.1 C67.2 PS6.4(+VO) R51.2 U26.1(VDD1)
AGND_ISO4: C61.2 C62.2 C67.1 D10.C PS6.3(0V) U26.8(GND1)
GND_3V3: C63.2 C64.2 C66.1 PS6.1(GND) U26.9(GND2) U26.16(2_GND2)  [also labelled GND_VCC]
NetC65_1: C65.1 R50.2 U26.3(VIN-)
NetC65_2: C65.2 R46.2 U26.2(VIN+)
NetD10_A: D10.A R51.1
NetR46_1: R46.1 R49.2 ; port ADC4_PLUS
NetR47_1: R47.1 ; port MDAT4
NetR47_2: R47.2 U26.11(MDAT)
NetR48_1: R48.1 ; port MCLKIN4
NetR48_2: R48.2 U26.13(MCLKIN)
NetR49_1: R49.1 R50.1 ; port ADC4_MINUS

Not connected (* = marked no-connect by the designer): U26 4(NC_4) 5(NC_5) 6(NC_6) 7(VDD1/NC) 10(NC_10) 12(NC_12) 15(NC_15)

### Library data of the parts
C61-C67 = CAP_0603
D10 = led_0603: as D1 on sheet SMPS_Supply
PS6 = B0505S-1WR3: as PS1 on sheet SMPS_Supply
R46-R48 R50 R51 = RES_0603: 1% 0.1W; MP: 1-2176071-4
R49 = RES_2512: 2512 1% 1W; MP: 1-2176071-4
U26 = AD7401YRWZ: as U27 on sheet SMPS_ADC_1

## Sheet SMPS_Signal.SchDoc
size A4; Organization: Altium Limited; Address1: L3, 12a Rodborough Rd; Address2: Frenchs Forest; Address3: NSW; Address4: Australia 2086; SheetNumber: 11; SheetTotal: 11
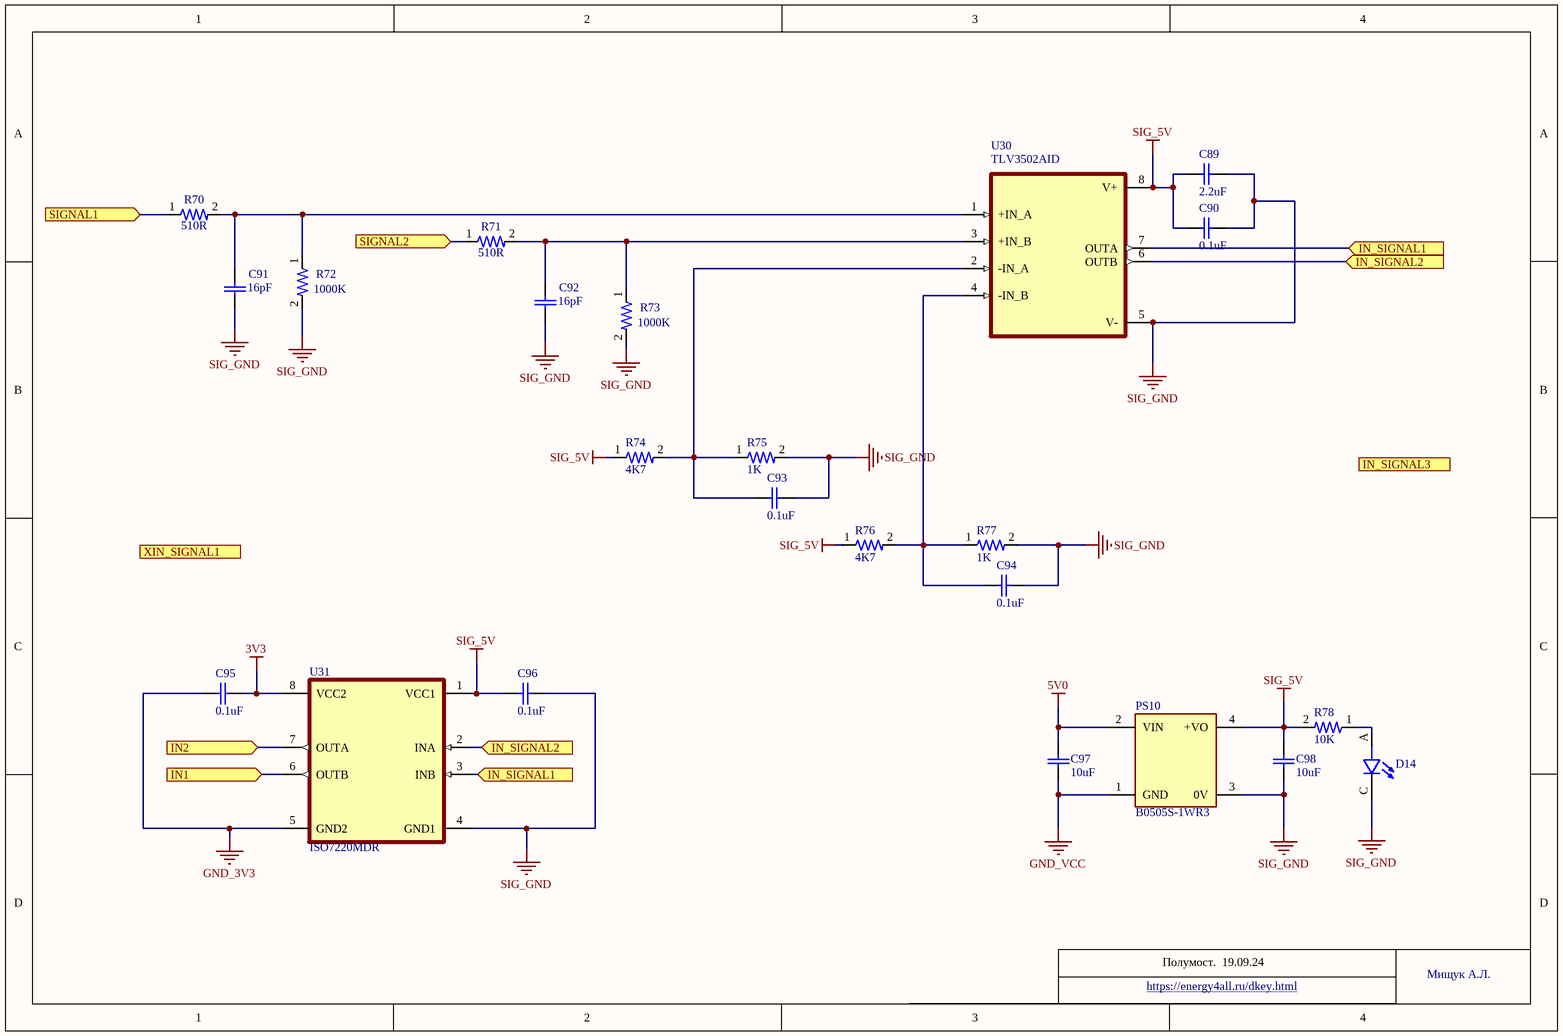
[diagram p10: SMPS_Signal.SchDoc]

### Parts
C89  2.2uF  [CAP_0603]
C90  0.1uF  [CAP_0603]
C91  16pF  [CAP_0603]
C92  16pF  [CAP_0603]
C93  0.1uF  [CAP_0603]
C94  0.1uF  [CAP_0603]
C95  0.1uF  [CAP_0603]
C96  0.1uF  [CAP_0603]
C97  10uF  [CAP_0603]
C98  10uF  [CAP_0603]
D14  led_0603  [led_0603]  (value not drawn)
PS10  B0505S-1WR3  [B0503S-1W]
R70  510R  [RESC1608X50N]
R71  510R  [RESC1608X50N]
R72  1000K  [RESC1608X50N]
R73  1000K  [RESC1608X50N]
R74  4K7  [RESC1608X50N]
R75  1K  [RESC1608X50N]
R76  4K7  [RESC1608X50N]
R77  1K  [RESC1608X50N]
R78  10K  [RESC1608X50N]
U30  TLV3502AID  [TLV3502AID]
U31  ISO7220MDR  [ISO7220MDR]

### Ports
IN1 (in), IN2 (in), IN_SIGNAL1 (in), IN_SIGNAL2 (in), IN_SIGNAL3 (in), SIGNAL1 (in), SIGNAL2 (in), XIN_SIGNAL1 (in)

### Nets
3V3: C95.1 U31.8(VCC2)
5V0: C97.2 PS10.2(VIN)
GND_3V3: C95.2 C97.1 PS10.1(GND) U31.5(GND2)  [also labelled GND_VCC]
SIG_5V: C89.1 C90.1 C96.2 C98.2 PS10.4(+VO) R74.1 R76.1 R78.2 U30.8(V+) U31.1(VCC1)
SIG_GND: C89.2 C90.2 C91.1 C92.1 C93.2 C94.2 C96.1 C98.1 D14.C PS10.3(0V) R72.2 R73.2 R75.2 R77.2 U30.5(V-) U31.4(GND1)
NetC91_2: C91.2 R70.2 R72.1 U30.1(+IN_A)
NetC92_2: C92.2 R71.2 R73.1 U30.3(+IN_B)
NetC93_1: C93.1 R74.2 R75.1 U30.2(-IN_A)
NetC94_1: C94.1 R76.2 R77.1 U30.4(-IN_B)
NetD14_A: D14.A R78.1
NetR70_1: R70.1 ; port SIGNAL1
NetR71_1: R71.1 ; port SIGNAL2
NetU3_B25: U31.6(OUTB) ; port IN1
NetU3_B26: U31.7(OUTA) ; port IN2
NetU30_6: U30.6(OUTB) U31.2(INA) ; port IN_SIGNAL2
NetU30_7: U30.7(OUTA) U31.3(INB) ; port IN_SIGNAL1

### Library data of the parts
C89-C98 = CAP_0603
D14 = led_0603: as D1 on sheet SMPS_Supply
PS10 = B0505S-1WR3: as PS1 on sheet SMPS_Supply
R70-R78 = RES_0603: 1% 0.1W; MP: 1-2176071-4
U30 = TLV3502AID: as U12 on sheet SMPS_Voltage_1
U31 = ISO7220MDR: as U15 on sheet SMPS_Voltage_1

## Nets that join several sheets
3V3: SMPS_Supply (7 pins), SMPS_Connector (8 pins), SMPS_Voltage_1 (5 pins), SMPS_Voltage_2 (5 pins), SMPS_Voltage_3 (5 pins), SMPS_Voltage_4 (5 pins), SMPS_ADC_1 (C70.1 C71.1 U27.14), SMPS_ADC_2 (C77.1 C78.1 U28.14), SMPS_ADC_3 (C84.1 C85.1 U29.14), SMPS_ADC_4 (C63.1 C64.1 U26.14), SMPS_Signal (C95.1 U31.8)
5V0: SMPS_Supply (5 pins), SMPS_Connector (C99.2 U3.A02), SMPS_Voltage_1 (C29.2 PS3.2), SMPS_Voltage_2 (C45.2 PS4.2), SMPS_Voltage_3 (C57.2 PS5.2), SMPS_Voltage_4 (C17.2 PS2.2), SMPS_ADC_1 (C73.2 PS7.2), SMPS_ADC_2 (C80.2 PS8.2), SMPS_ADC_3 (C87.2 PS9.2), SMPS_ADC_4 (C66.2 PS6.2), SMPS_Signal (C97.2 PS10.2)
GND_3V3: SMPS_Supply (12 pins), SMPS_Connector (20 pins), SMPS_Voltage_1 (7 pins), SMPS_Voltage_2 (7 pins), SMPS_Voltage_3 (7 pins), SMPS_Voltage_4 (7 pins), SMPS_ADC_1 (6 pins), SMPS_ADC_2 (6 pins), SMPS_ADC_3 (6 pins), SMPS_ADC_4 (6 pins), SMPS_Signal (C95.2 C97.1 PS10.1 U31.5)
SIG_GND: SMPS_Connector (U4.2 U4.4), SMPS_Signal (16 pins)
NetR46_1: SMPS_Connector (U2.2), SMPS_ADC_4 (R46.1 R49.2)
NetR47_1: SMPS_Connector (U3.A22), SMPS_ADC_4 (R47.1)
NetR48_1: SMPS_Connector (U3.A21), SMPS_ADC_4 (R48.1)
NetR49_1: SMPS_Connector (U2.1), SMPS_ADC_4 (R49.1 R50.1)
NetR52_1: SMPS_Connector (U2.8), SMPS_ADC_1 (R52.1 R55.2)
NetR53_1: SMPS_Connector (U3.A28), SMPS_ADC_1 (R53.1)
NetR54_1: SMPS_Connector (U3.A27), SMPS_ADC_1 (R54.1)
NetR55_1: SMPS_Connector (U2.7), SMPS_ADC_1 (R55.1 R56.1)
NetR58_1: SMPS_Connector (U2.6), SMPS_ADC_2 (R58.1 R61.2)
NetR59_1: SMPS_Connector (U3.A26), SMPS_ADC_2 (R59.1)
NetR60_1: SMPS_Connector (U3.A25), SMPS_ADC_2 (R60.1)
NetR61_1: SMPS_Connector (U2.5), SMPS_ADC_2 (R61.1 R62.1)
NetR64_1: SMPS_Connector (U2.4), SMPS_ADC_3 (R64.1 R67.2)
NetR65_1: SMPS_Connector (U3.A24), SMPS_ADC_3 (R65.1)
NetR66_1: SMPS_Connector (U3.A23), SMPS_ADC_3 (R66.1)
NetR67_1: SMPS_Connector (U2.3), SMPS_ADC_3 (R67.1 R68.1)
NetR70_1: SMPS_Connector (U4.1), SMPS_Signal (R70.1)
NetR71_1: SMPS_Connector (U4.3), SMPS_Signal (R71.1)
NetU3_B25: SMPS_Connector (U3.B25), SMPS_Signal (U31.6)
NetU3_B26: SMPS_Connector (U3.B26), SMPS_Signal (U31.7)
NetU3_C03: SMPS_Connector (U3.C03), SMPS_Voltage_1 (U15.6)
NetU3_C04: SMPS_Connector (U3.C04), SMPS_Voltage_1 (U15.7)
NetU3_C05: SMPS_Connector (U3.C05), SMPS_Voltage_1 (U11.5)
NetU3_C06: SMPS_Connector (U3.C06), SMPS_Voltage_2 (U16.6)
NetU3_C07: SMPS_Connector (U3.C07), SMPS_Voltage_2 (U16.7)
NetU3_C08: SMPS_Connector (U3.C08), SMPS_Voltage_2 (U20.5)
NetU3_C09: SMPS_Connector (U3.C09), SMPS_Voltage_3 (U25.7)
NetU3_C10: SMPS_Connector (U3.C10), SMPS_Voltage_3 (U25.6)
NetU3_C11: SMPS_Connector (U3.C11), SMPS_Voltage_4 (U10.6)
NetU3_C12: SMPS_Connector (U3.C12), SMPS_Voltage_3 (U21.5)
NetU3_C13: SMPS_Connector (U3.C13), SMPS_Voltage_4 (U6.5)
NetU3_C14: SMPS_Connector (U3.C14), SMPS_Voltage_4 (U10.7)
NetU3_C35: SMPS_Connector (U3.C35), SMPS_Voltage_1 (U11.3), SMPS_Voltage_2 (U20.3), SMPS_Voltage_3 (U21.3), SMPS_Voltage_4 (U6.3)
NetU3_C36: SMPS_Connector (U3.C36), SMPS_Voltage_1 (U11.4), SMPS_Voltage_2 (U20.4), SMPS_Voltage_3 (U21.4), SMPS_Voltage_4 (U6.4)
